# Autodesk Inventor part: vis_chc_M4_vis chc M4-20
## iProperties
Shininess: 64.0
Length Units: 11269
Angle Units: 11279
Time Units: 11290
Mass Units: 11283
Length Display Precision: 3
Angle Display Precision: 2
Compacted: True
Part Number: vis_chc_M4_vis chc M4-20
Document SubType Name: Modeling
Created: 2006-01
Material: Par défaut
Designer: riri
Density: 0.0
Volumn: 0.0
Area: 0.0
PropertySet Name: Model Information
Control State: 0
Master: False
Checked Out: False
Author: riri
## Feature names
1. Base1
